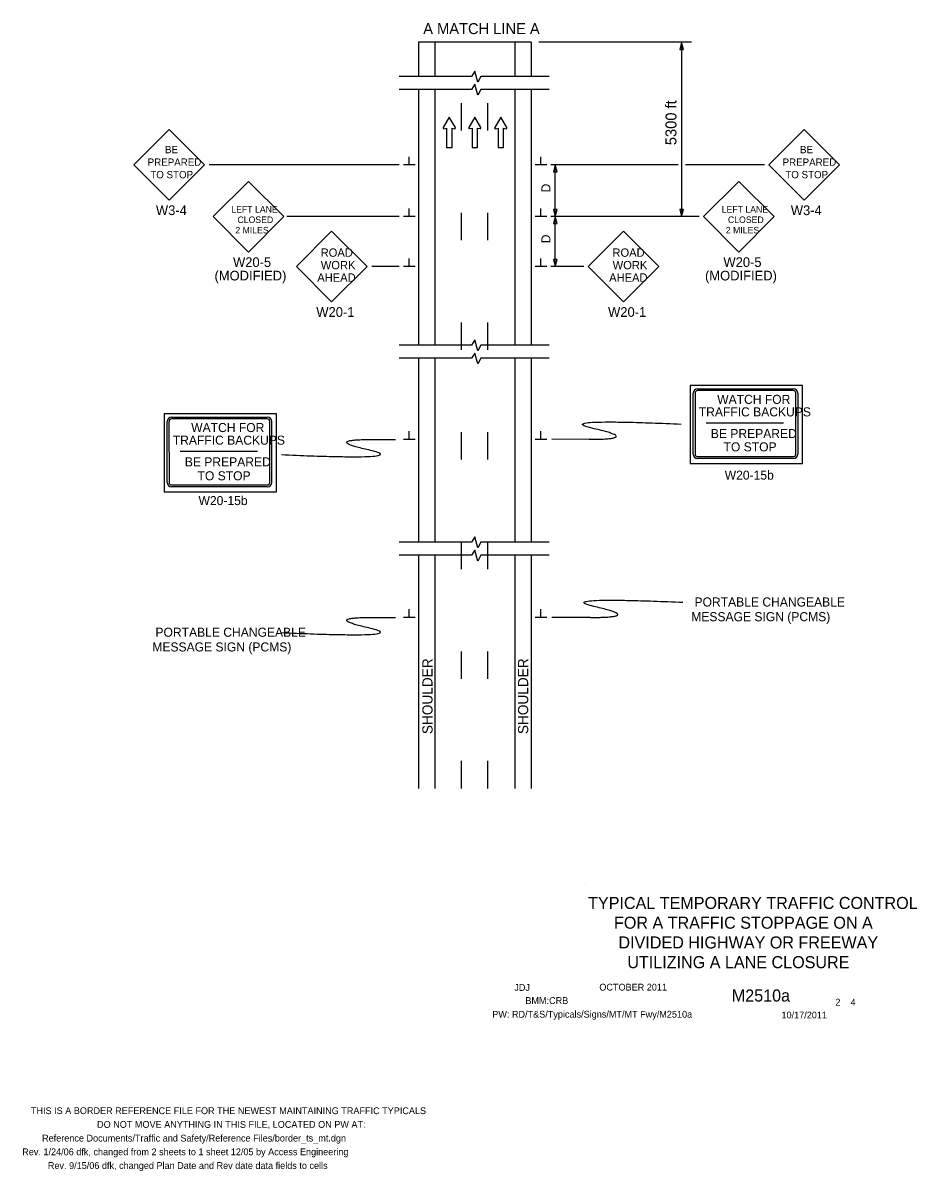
# Model space of a CAD drawing. Extents: x -1809 to 1557, y -1087 to 44.
# Drawn here: x -959 to -143, y -1087 to -39 of the extents above; entities that cross this region are included whole.
import ezdxf

# ---------------------------------------------------------------- set-up
doc = ezdxf.new("R2010")
doc.units = 0
for name, color, linetype in [('BORDER', 7, 'Continuous'), ('BORDER_SIGNAL_WO', 7, 'Continuous'), ('MT_SCRATCH_LEVEL_A', 7, 'Continuous'), ('MT_SCRATCH_LEVEL_E', 7, 'Continuous'), ('MT_STAGE_1A_NOTES', 7, 'Continuous'), ('PAVT_EDGE_EX', 7, 'Continuous'), ('PAVT_EDGE_PR', 7, 'Continuous'), ('SCRATCH_LEVEL_A', 7, 'Continuous'), ('TRAFFIC_SIGNS_PR', 7, 'Continuous'), ('TYPICAL_EX', 7, 'Continuous'), ('TYPICAL_TEXT_DIMEN_EX', 7, 'Continuous'), ('TYPICAL_TEXT_DIMEN_PR', 7, 'Continuous')]:
    doc.layers.add(name, color=color, linetype=linetype)

msp = doc.modelspace()

# ---------------------------------------------------------------- linework, layer by layer
at = {"layer": 'BORDER'}
for p, q in [((-509.7, -57.1), (-509.7, -88.2)), ((-509.7, -100.1), (-509.7, -333.4)), ((-558.7, -112.6), (-558.7, -137.6)), ((-534.7, -112.6), (-534.7, -137.6)), ((-558.7, -212.6), (-558.7, -237.6)), ((-534.7, -212.6), (-534.7, -237.6)), ((-558.7, -237.6), (-558.7, -237.6)), ((-534.7, -237.6), (-534.7, -237.6)), ((-558.7, -312.6), (-558.7, -337.6)), ((-534.7, -312.6), (-534.7, -337.6)), ((-509.7, -345.3), (-509.7, -513.1)), ((-558.7, -412.6), (-558.7, -437.6)), ((-534.7, -412.6), (-534.7, -437.6)), ((-558.7, -512.6), (-558.7, -537.6)), ((-534.7, -512.6), (-534.7, -537.6)), ((-509.7, -525), (-509.7, -737.6)), ((-558.7, -612.6), (-558.7, -637.6)), ((-534.7, -612.6), (-534.7, -637.6)), ((-558.7, -712.6), (-558.7, -737.6)), ((-534.7, -712.6), (-534.7, -737.6)), ((-445.2, -825.4), (-445.2, -825.4))]:
    msp.add_line(p, q, dxfattribs=at)
at = {"layer": 'MT_SCRATCH_LEVEL_A'}
for p, q in [((-582.7, -57.1), (-582.7, -88.2)), ((-582.7, -100.1), (-582.7, -333.4)), ((-582.7, -345.3), (-582.7, -513.1)), ((-582.7, -525), (-582.7, -737.6))]:
    msp.add_line(p, q, dxfattribs=at)
at = {"layer": 'MT_SCRATCH_LEVEL_E'}
for p, q in [((-569.7, -125.3), (-575.1, -134.9)), ((-564.1, -134.9), (-569.7, -125.3)), ((-546.4, -125.3), (-551.8, -134.9)), ((-540.8, -134.9), (-546.4, -125.3)), ((-522.6, -125.3), (-528.1, -134.9)), ((-517.1, -134.9), (-522.6, -125.3)), ((-574.5, -135.9), (-572.1, -135.4)), ((-572.1, -135.4), (-572.1, -153.1)), ((-567.1, -153.1), (-567.1, -135.4)), ((-567.1, -135.4), (-564.8, -135.9)), ((-551.2, -135.8), (-548.8, -135.4)), ((-548.8, -135.4), (-548.8, -153.1)), ((-543.8, -153.1), (-543.8, -135.4)), ((-543.8, -135.4), (-541.5, -135.8)), ((-527.5, -135.9), (-525.1, -135.4)), ((-525.1, -135.4), (-525.1, -153.1)), ((-520.1, -153.1), (-520.1, -135.4)), ((-520.1, -135.4), (-517.7, -135.9)), ((-572.1, -153.1), (-567.1, -153.1)), ((-548.8, -153.1), (-543.8, -153.1)), ((-525.1, -153.1), (-520.1, -153.1))]:
    msp.add_line(p, q, dxfattribs=at)
for centre, start, end in [((-574.6, -135.2), 150.4248, 279.9638), ((-564.7, -135.2), 260.0362, 29.7731), ((-551.3, -135.2), 150.4248, 279.9638), ((-541.4, -135.2), 260.0362, 29.7731), ((-527.6, -135.2), 150.4248, 279.9638), ((-517.6, -135.2), 260.0362, 29.7731)]:
    msp.add_arc(centre, 0.617, start, end, dxfattribs=at)
at = {"layer": 'MT_STAGE_1A_NOTES'}
for p, q in [((-357.6, -57.1), (-357.6, -216.1)), ((-615.3, -168.9), (-788.9, -168.9)), ((-360.7, -168.9), (-477, -168.9)), ((-473, -215.3), (-473, -168.9)), ((-282, -168.9), (-354, -168.9)), ((-615.3, -216.1), (-717.8, -216.1)), ((-341.5, -216.1), (-477, -216.1)), ((-473, -261.5), (-473, -215.6)), ((-615.3, -261.7), (-640.3, -261.7)), ((-446.9, -261.7), (-477, -261.7)), ((-638.7, -419.3), (-618.8, -419.3)), ((-442.1, -419.2), (-476, -419.3)), ((-638.7, -581.6), (-618.8, -581.6)), ((-440.7, -581.7), (-476, -581.6))]:
    msp.add_line(p, q, dxfattribs=at)
for points in [[(-442.1, -419.2), (-395, -419.2), (-479.3, -399.9), (-357.9, -405.3)], [(-722.9, -433.2), (-601, -438.5), (-685.6, -419.3), (-638.4, -419.3)], [(-440.7, -581.7), (-393.6, -581.7), (-478, -562.5), (-356.5, -567.8)], [(-722.9, -595.5), (-601, -600.9), (-685.6, -581.6), (-638.4, -581.6)]]:
    msp.add_open_spline(points, degree=2, dxfattribs=at)
at = {"layer": 'PAVT_EDGE_EX'}
for p, q in [((-597.8, -57.1), (-597.8, -88.2)), ((-494.9, -57.1), (-597.6, -57.1)), ((-494.9, -57.1), (-494.9, -88.2)), ((-597.8, -100.1), (-597.8, -333.4)), ((-494.9, -100.1), (-494.9, -333.4)), ((-597.8, -345.3), (-597.8, -513.1)), ((-494.9, -345.3), (-494.9, -513.1)), ((-597.8, -525), (-597.8, -737.6)), ((-494.9, -525), (-494.9, -737.6))]:
    msp.add_line(p, q, dxfattribs=at)
at = {"layer": 'PAVT_EDGE_PR'}
for points in [[(-342.2, -374.8), (-342.2, -374.8)], [(-342.2, -374.8), (-342.2, -374.8)], [(-822.3, -400.5), (-823.1, -400.5)], [(-822.3, -400.5), (-822.3, -400.5)], [(-822.3, -400.5), (-822.3, -400.5)]]:
    msp.add_lwpolyline(points, dxfattribs=at)
for centre in [(-342.6, -371.8), (-822.7, -397.6)]:
    msp.add_arc(centre, 2.95, 277.8103, 278.054, dxfattribs=at)
for points in [[(-349.7, -396.4), (-349.6, -396.4), (-349.5, -396.4), (-349.4, -396.4)], [(-829.8, -422.2), (-829.7, -422.2), (-829.6, -422.2), (-829.5, -422.2)]]:
    msp.add_open_spline(points, degree=2, dxfattribs=at)
at = {"layer": 'TRAFFIC_SIGNS_PR'}
for p, q in [((-825.2, -136.7), (-857.5, -168.9)), ((-793, -168.9), (-825.2, -136.7)), ((-245.7, -136.7), (-277.9, -168.9)), ((-213.4, -168.9), (-245.7, -136.7)), ((-857.5, -168.9), (-825.2, -201.1)), ((-825.2, -201.1), (-793, -168.9)), ((-277.9, -168.9), (-245.7, -201.1)), ((-245.7, -201.1), (-213.4, -168.9)), ((-753, -183.9), (-785.2, -216.1)), ((-720.7, -216.1), (-753, -183.9)), ((-305.3, -183.9), (-337.6, -216.1)), ((-273.1, -216.1), (-305.3, -183.9)), ((-785.2, -216.1), (-753, -248.4)), ((-753, -248.4), (-720.7, -216.1)), ((-337.6, -216.1), (-305.3, -248.4)), ((-305.3, -248.4), (-273.1, -216.1)), ((-677, -229.4), (-709.2, -261.7)), ((-644.7, -261.7), (-677, -229.4)), ((-410.6, -229.4), (-442.9, -261.7)), ((-378.4, -261.7), (-410.6, -229.4)), ((-709.2, -261.7), (-677, -293.9)), ((-677, -293.9), (-644.7, -261.7)), ((-442.9, -261.7), (-410.6, -293.9)), ((-410.6, -293.9), (-378.4, -261.7)), ((-335.3, -404.3), (-264.6, -404.3)), ((-815.4, -430.1), (-744.7, -430.1))]:
    msp.add_line(p, q, dxfattribs=at)
for points in [[(-349.7, -441.2), (-247.3, -441.2), (-247.3, -370.1), (-349.7, -370.1)], [(-829.8, -467), (-727.4, -467), (-727.4, -395.9), (-829.8, -395.9)]]:
    msp.add_lwpolyline(points, close=True, dxfattribs=at)
for points in [[(-343, -373.2), (-343, -373.2), (-342.8, -373.2), (-342.8, -373.2), (-255.6, -373.2)], [(-342.2, -374.8), (-343, -374.8)], [(-255.7, -374.8), (-342.2, -374.8)], [(-346.9, -432.8), (-346.9, -377.2), (-346.9, -377.2)], [(-345.3, -377.1), (-345.3, -377.5), (-345.3, -377.7), (-345.3, -377.8), (-345.3, -377.9), (-345.3, -432.7)], [(-345.3, -377.5), (-345.3, -377.5)], [(-253.4, -432.7), (-253.4, -377.1)], [(-251.6, -377.2), (-251.6, -432.8)], [(-827.1, -458.6), (-827.1, -403), (-827, -403)], [(-825.4, -402.9), (-825.5, -403.3), (-825.4, -403.5), (-825.4, -403.6), (-825.5, -403.7), (-825.4, -458.5)], [(-825.5, -403.3), (-825.4, -403.3)], [(-823.1, -399), (-823.1, -399), (-822.9, -399), (-822.9, -399), (-735.7, -399)], [(-735.8, -400.5), (-822.3, -400.5)], [(-733.5, -458.5), (-733.5, -402.9)], [(-731.8, -403), (-731.8, -458.6)], [(-343, -435), (-255.7, -435)], [(-255.6, -436.7), (-343, -436.7)], [(-823.1, -460.8), (-735.8, -460.8)], [(-735.7, -462.5), (-823.1, -462.5)]]:
    msp.add_lwpolyline(points, dxfattribs=at)
for centre, radius, start, end in [((-343, -377.2), 3.97, 90.2048, 180), ((-343, -377.1), 2.32, 90, 180), ((-255.7, -377.1), 2.32, 0, 90), ((-255.6, -377.2), 3.97, 360, 90), ((-823.1, -403), 3.97, 90.2048, 180), ((-823.1, -402.9), 2.32, 90, 180), ((-735.8, -402.9), 2.32, 0, 90), ((-735.7, -403), 3.97, 360, 90), ((-343, -432.8), 3.97, 180, 270), ((-343, -432.7), 2.32, 180, 270), ((-255.7, -432.7), 2.32, 270, 360), ((-255.6, -432.8), 3.97, 270, 0), ((-823.1, -458.6), 3.97, 180, 270), ((-823.1, -458.5), 2.32, 180, 270), ((-735.8, -458.5), 2.32, 270, 360), ((-735.7, -458.6), 3.97, 270, 0)]:
    msp.add_arc(centre, radius, start, end, dxfattribs=at)
at = {"layer": 'TYPICAL_EX'}
for p, q in [((-606.1, -168.9), (-606.1, -161.5)), ((-486, -168.9), (-486, -161.5)), ((-606.1, -168.9), (-611.4, -168.9)), ((-600.8, -168.9), (-606.1, -168.9)), ((-486, -168.9), (-491.3, -168.9)), ((-480.7, -168.9), (-486, -168.9)), ((-606.1, -216.1), (-606.1, -208.7)), ((-486, -216.1), (-486, -208.7)), ((-606.1, -216.1), (-611.4, -216.1)), ((-600.8, -216.1), (-606.1, -216.1)), ((-486, -216.1), (-491.3, -216.1)), ((-480.7, -216.1), (-486, -216.1)), ((-606.1, -261.7), (-611.4, -261.7)), ((-606.1, -261.7), (-606.1, -254.3)), ((-600.8, -261.7), (-606.1, -261.7)), ((-486, -261.7), (-491.3, -261.7)), ((-486, -261.7), (-486, -254.3)), ((-480.7, -261.7), (-486, -261.7)), ((-606.1, -419.3), (-606.1, -411.9)), ((-486, -419.3), (-486, -411.9)), ((-606.1, -419.3), (-611.4, -419.3)), ((-600.8, -419.3), (-606.1, -419.3)), ((-486, -419.3), (-491.3, -419.3)), ((-480.7, -419.3), (-486, -419.3)), ((-606.1, -581.6), (-606.1, -574.2)), ((-486, -581.6), (-486, -574.2)), ((-606.1, -581.6), (-611.4, -581.6)), ((-600.8, -581.6), (-606.1, -581.6)), ((-486, -581.6), (-491.3, -581.6)), ((-480.7, -581.6), (-486, -581.6))]:
    msp.add_line(p, q, dxfattribs=at)
at = {"layer": 'TYPICAL_TEXT_DIMEN_PR'}
for p, q in [((-348.5, -57.1), (-488, -57.1)), ((-357.6, -57.1), (-359.3, -63.5)), ((-355.9, -63.5), (-357.6, -57.1)), ((-359.3, -63.5), (-357.6, -63.5)), ((-357.6, -63.5), (-355.9, -63.5)), ((-546.3, -83.4), (-549.5, -88.2)), ((-543.5, -93.4), (-546.3, -83.4)), ((-549.5, -88.2), (-615.5, -88.2)), ((-540.8, -88.2), (-543.5, -93.4)), ((-478.5, -88.2), (-540.8, -88.2)), ((-549.5, -100.1), (-615.5, -100.1)), ((-546.3, -95.3), (-549.5, -100.1)), ((-543.5, -105.3), (-546.3, -95.3)), ((-540.8, -100.1), (-543.5, -105.3)), ((-478.5, -100.1), (-540.8, -100.1)), ((-473, -168.9), (-474.6, -175.3)), ((-474.6, -175.3), (-473, -175.3)), ((-471.3, -175.3), (-473, -168.9)), ((-473, -175.3), (-471.3, -175.3)), ((-473, -209.7), (-474.6, -209.7)), ((-474.6, -209.7), (-473, -216.1)), ((-473, -216.1), (-474.6, -222.5)), ((-473, -216.1), (-471.3, -209.7)), ((-471.3, -209.7), (-473, -209.7)), ((-471.3, -222.5), (-473, -216.1)), ((-357.6, -209.7), (-359.3, -209.7)), ((-359.3, -209.7), (-357.6, -216.1)), ((-357.6, -216.1), (-355.9, -209.7)), ((-355.9, -209.7), (-357.6, -209.7)), ((-474.6, -222.5), (-473, -222.5)), ((-473, -222.5), (-471.3, -222.5)), ((-473, -255.2), (-474.6, -255.2)), ((-474.6, -255.2), (-473, -261.7)), ((-473, -261.7), (-471.3, -255.2)), ((-471.3, -255.2), (-473, -255.2)), ((-549.5, -333.4), (-615.5, -333.4)), ((-546.3, -328.6), (-549.5, -333.4)), ((-543.5, -338.5), (-546.3, -328.6)), ((-540.8, -333.4), (-543.5, -338.5)), ((-478.5, -333.4), (-540.8, -333.4)), ((-549.5, -345.3), (-615.5, -345.3)), ((-546.3, -340.5), (-549.5, -345.3)), ((-543.5, -350.4), (-546.3, -340.5)), ((-540.8, -345.3), (-543.5, -350.4)), ((-478.5, -345.3), (-540.8, -345.3)), ((-549.5, -513.1), (-615.5, -513.1)), ((-546.3, -508.3), (-549.5, -513.1)), ((-543.5, -518.2), (-546.3, -508.3)), ((-540.8, -513.1), (-543.5, -518.2)), ((-478.5, -513.1), (-540.8, -513.1)), ((-546.3, -520.2), (-549.5, -525)), ((-543.5, -530.2), (-546.3, -520.2)), ((-549.5, -525), (-615.5, -525)), ((-540.8, -525), (-543.5, -530.2)), ((-478.5, -525), (-540.8, -525))]:
    msp.add_line(p, q, dxfattribs=at)

# ---------------------------------------------------------------- texts
at = {"layer": 'BORDER_SIGNAL_WO'}
for s, height, p in [('TYPICAL TEMPORARY TRAFFIC CONTROL', 11, (-442.9, -847.6)), ('FOR A TRAFFIC STOPPAGE ON A', 11, (-419.3, -865.6)), ('DIVIDED HIGHWAY OR FREEWAY', 11, (-415.2, -883.6)), ('UTILIZING A LANE CLOSURE', 11, (-407.1, -901.6)), ('JDJ         ', 6.2, (-510.3, -922.3)), ('    OCTOBER 2011', 6.2, (-441.9, -922)), ('    M2510a   ', 11, (-328.1, -932)), ('BMM:CRB', 6.2, (-500.2, -934.2)), (' 2    4 ', 6.2, (-219.5, -935.7)), ('PW: RD/T&S/Typicals/Signs/MT/MT Fwy/M2510a     ', 6.2, (-530.4, -946.7)), ('10/17/2011', 6.2, (-266.4, -947.4))]:
    msp.add_text(s, height=height, dxfattribs=at).set_placement(p)
at = {"layer": 'MT_STAGE_1A_NOTES'}
for s, height, p in [('5300 ft', 10, (-362.3, -150.9)), ('D', 8.25, (-477.3, -194)), ('D', 8.25, (-477.3, -240.4))]:
    msp.add_text(s, height=height, rotation=90, dxfattribs=at).set_placement(p)
at = {"layer": 'SCRATCH_LEVEL_A'}
for s, p in [('THIS IS A BORDER REFERENCE FILE FOR THE NEWEST MAINTAINING TRAFFIC TYPICALS', (-951.5, -1034.7)), ('DO NOT MOVE ANYTHING IN THIS FILE, LOCATED ON PW AT:', (-891.1, -1047.2)), ('Reference Documents/Traffic and Safety/Reference Files/border_ts_mt.dgn', (-941.3, -1059.7)), ('Rev. 1/24/06 dfk, changed from 2 sheets to 1 sheet 12/05 by Access Engineering', (-959.4, -1072.2)), ('Rev. 9/15/06 dfk, changed Plan Date and Rev date data fields to cells', (-936, -1084.7))]:
    msp.add_text(s, height=6.2, dxfattribs=at).set_placement(p)
at = {"layer": 'TRAFFIC_SIGNS_PR'}
for s, height, p in [('BE', 6.65, (-829.1, -158.3)), ('BE', 6.65, (-249.5, -158.3)), ('PREPARED', 6.65, (-844.9, -169.7)), ('PREPARED', 6.65, (-265.4, -169.7)), ('TO STOP', 6.65, (-842.5, -181.1)), ('TO STOP', 6.65, (-262.9, -181.1)), ('W3-4', 8.84, (-837.4, -214.7)), ('LEFT LANE', 5.94, (-768.6, -212.4)), ('LEFT LANE', 5.94, (-321, -212.4)), ('W3-4', 8.84, (-257.9, -214.7)), ('CLOSED', 5.94, (-763, -221.9)), ('CLOSED', 5.94, (-315.3, -221.9)), ('2 MILES', 5.94, (-764.9, -231.4)), ('2 MILES', 5.94, (-317.2, -231.4)), ('ROAD', 7.6, (-687, -252.7)), ('ROAD', 7.6, (-420.7, -252.7)), ('W20-5', 8.83, (-767, -262)), ('WORK', 7.6, (-686.9, -264.1)), ('WORK', 7.6, (-420.5, -264.1)), ('W20-5', 8.83, (-319.4, -262)), ('(MODIFIED)', 8.83, (-783.9, -274.3)), ('AHEAD', 7.6, (-690.1, -275.5)), ('AHEAD', 7.6, (-423.7, -275.5)), ('(MODIFIED)', 8.83, (-336.2, -274.3)), ('W20-1', 8.84, (-691, -307.5)), ('W20-1', 8.84, (-424.7, -307.5)), ('WATCH FOR', 8.25, (-325.1, -386.9)), ('TRAFFIC BACKUPS', 8.25, (-341.9, -398.3)), ('WATCH FOR', 8.25, (-805.2, -412.6)), ('TRAFFIC BACKUPS', 8.25, (-822, -424.1)), ('BE PREPARED', 8.25, (-330.9, -418.1)), ('TO STOP', 8.25, (-319.3, -430.2)), ('BE PREPARED', 8.25, (-811, -443.9)), ('TO STOP', 8.25, (-799.4, -456.6)), ('W20-15b', 8.25, (-318.2, -456)), ('W20-15b', 8.25, (-798.5, -479.2)), ('PORTABLE CHANGEABLE', 8.25, (-345.8, -571.7)), ('  MESSAGE SIGN (PCMS)', 8.25, (-354.9, -585.1)), ('PORTABLE CHANGEABLE', 8.25, (-837.8, -599.3)), ('  MESSAGE SIGN (PCMS)', 8.25, (-846.8, -612.7))]:
    msp.add_text(s, height=height, dxfattribs=at).set_placement(p)
at = {"layer": 'TYPICAL_TEXT_DIMEN_EX'}
msp.add_text('A MATCH LINE A', height=10, dxfattribs=at).set_placement((-593.4, -49.6))
for p in [(-584.9, -688.1), (-497.6, -688.1)]:
    msp.add_text('SHOULDER', height=9.3, rotation=90, dxfattribs=at).set_placement(p)

doc.saveas('drawing.dxf')
